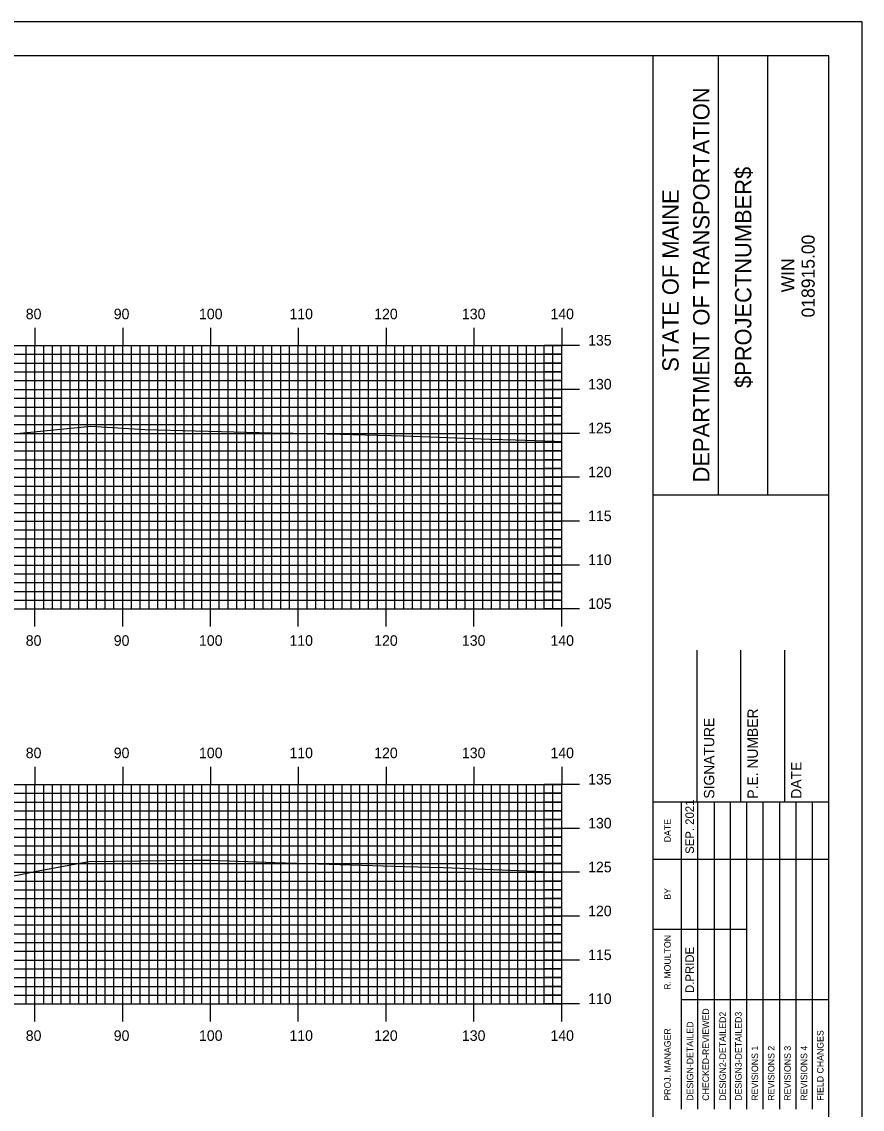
# Model space of a CAD drawing. Extents: x 843356 to 843699, y 363538 to 363758.
# Drawn here: x 843599.9 to 843695.6, y 363633.7 to 363757.6 of the extents above; entities that cross this region are included whole.
import ezdxf

# ---------------------------------------------------------------- set-up
doc = ezdxf.new("R2010")
doc.units = 0
for name, color, linetype in [('BORDER', 7, 'Continuous'), ('H_V ANNOTATION', 7, 'Continuous'), ('MAJOR', 7, 'Continuous'), ('MINOR', 7, 'Continuous'), ('PLOT BOUNDARY', 7, 'Continuous'), ('S_Roadway_Centerline', 7, 'Continuous')]:
    doc.layers.add(name, color=color, linetype=linetype)

msp = doc.modelspace()

# ---------------------------------------------------------------- linework, layer by layer
at = {"layer": 'BORDER'}
for p, q in [((843671.82, 363543.72), (843671.82, 363753.72)), ((843679.28, 363703.72), (843679.28, 363753.72)), ((843684.87, 363703.72), (843684.87, 363753.72)), ((843671.83, 363703.71), (843691.82, 363703.71)), ((843676.82, 363668.73), (843676.82, 363686.02)), ((843681.82, 363668.73), (843681.82, 363686.02)), ((843686.82, 363668.73), (843686.82, 363686.02)), ((843671.82, 363668.73), (843691.82, 363668.73))]:
    msp.add_line(p, q, dxfattribs=at)
msp.add_lwpolyline([(843371.82, 363543.72), (843691.82, 363543.72), (843691.82, 363753.72), (843371.82, 363753.72)], close=True, dxfattribs=at)
for points in [[(843675.05, 363662.23), (843675.05, 363668.73)], [(843676.92, 363633.73), (843676.92, 363668.73)], [(843678.78, 363668.73), (843678.78, 363633.73)], [(843680.65, 363633.73), (843680.65, 363668.73)], [(843682.51, 363633.73), (843682.51, 363668.73)], [(843684.37, 363633.73), (843684.37, 363668.73)], [(843686.24, 363633.73), (843686.24, 363668.73)], [(843688.1, 363633.73), (843688.1, 363668.73)], [(843689.96, 363633.73), (843689.96, 363668.73)], [(843675.06, 363633.73), (843675.06, 363667.31)], [(843671.82, 363662.23), (843691.82, 363662.23)], [(843671.82, 363654.23), (843675.06, 363654.23)], [(843675.05, 363654.23), (843682.51, 363654.23)], [(843675.05, 363646.23), (843691.82, 363646.23)]]:
    msp.add_lwpolyline(points, dxfattribs=at)
at = {"layer": 'MAJOR'}
for p, q in [((843601.42, 363722.73), (843601.42, 363720.72)), ((843611.42, 363722.73), (843611.42, 363720.72)), ((843621.42, 363722.73), (843621.42, 363720.72)), ((843631.42, 363722.73), (843631.42, 363720.72)), ((843641.42, 363722.73), (843641.42, 363720.72)), ((843651.42, 363722.73), (843651.42, 363720.72)), ((843661.42, 363722.73), (843661.42, 363720.72)), ((843381.42, 363720.72), (843661.42, 363720.72)), ((843381.42, 363720.72), (843661.42, 363720.72)), ((843601.42, 363690.72), (843601.42, 363720.72)), ((843611.42, 363690.72), (843611.42, 363720.72)), ((843621.42, 363690.72), (843621.42, 363720.72)), ((843631.42, 363690.72), (843631.42, 363720.72)), ((843641.42, 363690.72), (843641.42, 363720.72)), ((843651.42, 363690.72), (843651.42, 363720.72)), ((843663.43, 363720.72), (843659.42, 363720.72)), ((843661.42, 363690.72), (843661.42, 363720.72)), ((843661.42, 363690.72), (843661.42, 363720.72)), ((843381.42, 363715.72), (843661.42, 363715.72)), ((843663.43, 363715.72), (843659.42, 363715.72)), ((843381.42, 363710.72), (843661.42, 363710.72)), ((843663.43, 363710.72), (843659.42, 363710.72)), ((843381.42, 363705.72), (843661.42, 363705.72)), ((843663.43, 363705.72), (843659.42, 363705.72)), ((843381.42, 363700.72), (843661.42, 363700.72)), ((843663.43, 363700.72), (843659.42, 363700.72)), ((843381.42, 363695.72), (843661.42, 363695.72)), ((843663.43, 363695.72), (843659.42, 363695.72)), ((843381.42, 363690.72), (843661.42, 363690.72)), ((843381.42, 363690.72), (843661.42, 363690.72)), ((843601.42, 363688.72), (843601.42, 363690.72)), ((843611.42, 363688.72), (843611.42, 363690.72)), ((843621.42, 363688.72), (843621.42, 363690.72)), ((843631.42, 363688.72), (843631.42, 363690.72)), ((843641.42, 363688.72), (843641.42, 363690.72)), ((843651.42, 363688.72), (843651.42, 363690.72)), ((843663.43, 363690.72), (843659.42, 363690.72)), ((843661.42, 363688.72), (843661.42, 363690.72)), ((843601.42, 363672.73), (843601.42, 363670.72)), ((843611.42, 363672.73), (843611.42, 363670.72)), ((843621.42, 363672.73), (843621.42, 363670.72)), ((843631.42, 363672.73), (843631.42, 363670.72)), ((843641.42, 363672.73), (843641.42, 363670.72)), ((843651.42, 363672.73), (843651.42, 363670.72)), ((843661.42, 363672.73), (843661.42, 363670.72)), ((843381.42, 363670.72), (843661.42, 363670.72)), ((843381.42, 363670.72), (843661.42, 363670.72)), ((843601.42, 363645.72), (843601.42, 363670.72)), ((843611.42, 363645.72), (843611.42, 363670.72)), ((843621.42, 363645.72), (843621.42, 363670.72)), ((843631.42, 363645.72), (843631.42, 363670.72)), ((843641.42, 363645.72), (843641.42, 363670.72)), ((843651.42, 363645.72), (843651.42, 363670.72)), ((843663.43, 363670.72), (843659.42, 363670.72)), ((843661.42, 363645.72), (843661.42, 363670.72)), ((843661.42, 363645.72), (843661.42, 363670.72)), ((843381.42, 363665.72), (843661.42, 363665.72)), ((843663.43, 363665.72), (843659.42, 363665.72)), ((843381.42, 363660.72), (843661.42, 363660.72)), ((843663.43, 363660.72), (843659.42, 363660.72)), ((843381.42, 363655.72), (843661.42, 363655.72)), ((843663.43, 363655.72), (843659.42, 363655.72)), ((843381.42, 363650.72), (843661.42, 363650.72)), ((843663.43, 363650.72), (843659.42, 363650.72)), ((843381.42, 363645.72), (843661.42, 363645.72)), ((843381.42, 363645.72), (843661.42, 363645.72)), ((843601.42, 363643.72), (843601.42, 363645.72)), ((843611.42, 363643.72), (843611.42, 363645.72)), ((843621.42, 363643.72), (843621.42, 363645.72)), ((843631.42, 363643.72), (843631.42, 363645.72)), ((843641.42, 363643.72), (843641.42, 363645.72)), ((843651.42, 363643.72), (843651.42, 363645.72)), ((843663.43, 363645.72), (843659.42, 363645.72)), ((843661.42, 363643.72), (843661.42, 363645.72))]:
    msp.add_line(p, q, dxfattribs=at)
at = {"layer": 'MINOR'}
for p, q in [((843600.42, 363690.72), (843600.42, 363720.72)), ((843602.42, 363690.72), (843602.42, 363720.72)), ((843603.42, 363690.72), (843603.42, 363720.72)), ((843604.42, 363690.72), (843604.42, 363720.72)), ((843605.42, 363690.72), (843605.42, 363720.72)), ((843606.42, 363690.72), (843606.42, 363720.72)), ((843607.42, 363690.72), (843607.42, 363720.72)), ((843608.42, 363690.72), (843608.42, 363720.72)), ((843609.42, 363690.72), (843609.42, 363720.72)), ((843610.42, 363690.72), (843610.42, 363720.72)), ((843612.42, 363690.72), (843612.42, 363720.72)), ((843613.42, 363690.72), (843613.42, 363720.72)), ((843614.42, 363690.72), (843614.42, 363720.72)), ((843615.42, 363690.72), (843615.42, 363720.72)), ((843616.42, 363690.72), (843616.42, 363720.72)), ((843617.42, 363690.72), (843617.42, 363720.72)), ((843618.42, 363690.72), (843618.42, 363720.72)), ((843619.42, 363690.72), (843619.42, 363720.72)), ((843620.42, 363690.72), (843620.42, 363720.72)), ((843622.42, 363690.72), (843622.42, 363720.72)), ((843623.42, 363690.72), (843623.42, 363720.72)), ((843624.42, 363690.72), (843624.42, 363720.72)), ((843625.42, 363690.72), (843625.42, 363720.72)), ((843626.42, 363690.72), (843626.42, 363720.72)), ((843627.42, 363690.72), (843627.42, 363720.72)), ((843628.42, 363690.72), (843628.42, 363720.72)), ((843629.42, 363690.72), (843629.42, 363720.72)), ((843630.42, 363690.72), (843630.42, 363720.72)), ((843632.42, 363690.72), (843632.42, 363720.72)), ((843633.42, 363690.72), (843633.42, 363720.72)), ((843634.42, 363690.72), (843634.42, 363720.72)), ((843635.42, 363690.72), (843635.42, 363720.72)), ((843636.42, 363690.72), (843636.42, 363720.72)), ((843637.42, 363690.72), (843637.42, 363720.72)), ((843638.42, 363690.72), (843638.42, 363720.72)), ((843639.42, 363690.72), (843639.42, 363720.72)), ((843640.42, 363690.72), (843640.42, 363720.72)), ((843642.42, 363690.72), (843642.42, 363720.72)), ((843643.42, 363690.72), (843643.42, 363720.72)), ((843644.42, 363690.72), (843644.42, 363720.72)), ((843645.42, 363690.72), (843645.42, 363720.72)), ((843646.42, 363690.72), (843646.42, 363720.72)), ((843647.42, 363690.72), (843647.42, 363720.72)), ((843648.42, 363690.72), (843648.42, 363720.72)), ((843649.42, 363690.72), (843649.42, 363720.72)), ((843650.42, 363690.72), (843650.42, 363720.72)), ((843652.42, 363690.72), (843652.42, 363720.72)), ((843653.42, 363690.72), (843653.42, 363720.72)), ((843654.42, 363690.72), (843654.42, 363720.72)), ((843655.42, 363690.72), (843655.42, 363720.72)), ((843656.42, 363690.72), (843656.42, 363720.72)), ((843657.42, 363690.72), (843657.42, 363720.72)), ((843658.42, 363690.72), (843658.42, 363720.72)), ((843659.42, 363690.72), (843659.42, 363720.72)), ((843660.42, 363690.72), (843660.42, 363720.72)), ((843381.42, 363719.72), (843661.42, 363719.72)), ((843661.42, 363719.72), (843659.42, 363719.72)), ((843381.42, 363718.72), (843661.42, 363718.72)), ((843661.42, 363718.72), (843659.42, 363718.72)), ((843381.42, 363717.72), (843661.42, 363717.72)), ((843381.42, 363716.72), (843661.42, 363716.72)), ((843661.42, 363717.72), (843659.42, 363717.72)), ((843661.42, 363716.72), (843659.42, 363716.72)), ((843381.42, 363714.72), (843661.42, 363714.72)), ((843661.42, 363714.72), (843659.42, 363714.72)), ((843381.42, 363713.72), (843661.42, 363713.72)), ((843661.42, 363713.72), (843659.42, 363713.72)), ((843381.42, 363712.72), (843661.42, 363712.72)), ((843381.42, 363711.72), (843661.42, 363711.72)), ((843661.42, 363712.72), (843659.42, 363712.72)), ((843661.42, 363711.72), (843659.42, 363711.72)), ((843381.42, 363709.72), (843661.42, 363709.72)), ((843661.42, 363709.72), (843659.42, 363709.72)), ((843381.42, 363708.72), (843661.42, 363708.72)), ((843661.42, 363708.72), (843659.42, 363708.72)), ((843381.42, 363707.72), (843661.42, 363707.72)), ((843381.42, 363706.72), (843661.42, 363706.72)), ((843661.42, 363707.72), (843659.42, 363707.72)), ((843661.42, 363706.72), (843659.42, 363706.72)), ((843381.42, 363704.72), (843661.42, 363704.72)), ((843661.42, 363704.72), (843659.42, 363704.72)), ((843381.42, 363703.72), (843661.42, 363703.72)), ((843661.42, 363703.72), (843659.42, 363703.72)), ((843381.42, 363702.72), (843661.42, 363702.72)), ((843661.42, 363702.72), (843659.42, 363702.72)), ((843381.42, 363701.72), (843661.42, 363701.72)), ((843661.42, 363701.72), (843659.42, 363701.72)), ((843381.42, 363699.72), (843661.42, 363699.72)), ((843661.42, 363699.72), (843659.42, 363699.72)), ((843381.42, 363698.72), (843661.42, 363698.72)), ((843661.42, 363698.72), (843659.42, 363698.72)), ((843381.42, 363697.72), (843661.42, 363697.72)), ((843661.42, 363697.72), (843659.42, 363697.72)), ((843381.42, 363696.72), (843661.42, 363696.72)), ((843661.42, 363696.72), (843659.42, 363696.72)), ((843381.42, 363694.72), (843661.42, 363694.72)), ((843661.42, 363694.72), (843659.42, 363694.72)), ((843381.42, 363693.72), (843661.42, 363693.72)), ((843661.42, 363693.72), (843659.42, 363693.72)), ((843381.42, 363692.72), (843661.42, 363692.72)), ((843661.42, 363692.72), (843659.42, 363692.72)), ((843381.42, 363691.72), (843661.42, 363691.72)), ((843661.42, 363691.72), (843659.42, 363691.72)), ((843381.42, 363669.72), (843661.42, 363669.72)), ((843600.42, 363645.72), (843600.42, 363670.72)), ((843602.42, 363645.72), (843602.42, 363670.72)), ((843603.42, 363645.72), (843603.42, 363670.72)), ((843604.42, 363645.72), (843604.42, 363670.72)), ((843605.42, 363645.72), (843605.42, 363670.72)), ((843606.42, 363645.72), (843606.42, 363670.72)), ((843607.42, 363645.72), (843607.42, 363670.72)), ((843608.42, 363645.72), (843608.42, 363670.72)), ((843609.42, 363645.72), (843609.42, 363670.72)), ((843610.42, 363645.72), (843610.42, 363670.72)), ((843612.42, 363645.72), (843612.42, 363670.72)), ((843613.42, 363645.72), (843613.42, 363670.72)), ((843614.42, 363645.72), (843614.42, 363670.72)), ((843615.42, 363645.72), (843615.42, 363670.72)), ((843616.42, 363645.72), (843616.42, 363670.72)), ((843617.42, 363645.72), (843617.42, 363670.72)), ((843618.42, 363645.72), (843618.42, 363670.72)), ((843619.42, 363645.72), (843619.42, 363670.72)), ((843620.42, 363645.72), (843620.42, 363670.72)), ((843622.42, 363645.72), (843622.42, 363670.72)), ((843623.42, 363645.72), (843623.42, 363670.72)), ((843624.42, 363645.72), (843624.42, 363670.72)), ((843625.42, 363645.72), (843625.42, 363670.72)), ((843626.42, 363645.72), (843626.42, 363670.72)), ((843627.42, 363645.72), (843627.42, 363670.72)), ((843628.42, 363645.72), (843628.42, 363670.72)), ((843629.42, 363645.72), (843629.42, 363670.72)), ((843630.42, 363645.72), (843630.42, 363670.72)), ((843632.42, 363645.72), (843632.42, 363670.72)), ((843633.42, 363645.72), (843633.42, 363670.72)), ((843634.42, 363645.72), (843634.42, 363670.72)), ((843635.42, 363645.72), (843635.42, 363670.72)), ((843636.42, 363645.72), (843636.42, 363670.72)), ((843637.42, 363645.72), (843637.42, 363670.72)), ((843638.42, 363645.72), (843638.42, 363670.72)), ((843639.42, 363645.72), (843639.42, 363670.72)), ((843640.42, 363645.72), (843640.42, 363670.72)), ((843642.42, 363645.72), (843642.42, 363670.72)), ((843643.42, 363645.72), (843643.42, 363670.72)), ((843644.42, 363645.72), (843644.42, 363670.72)), ((843645.42, 363645.72), (843645.42, 363670.72)), ((843646.42, 363645.72), (843646.42, 363670.72)), ((843647.42, 363645.72), (843647.42, 363670.72)), ((843648.42, 363645.72), (843648.42, 363670.72)), ((843649.42, 363645.72), (843649.42, 363670.72)), ((843650.42, 363645.72), (843650.42, 363670.72)), ((843652.42, 363645.72), (843652.42, 363670.72)), ((843653.42, 363645.72), (843653.42, 363670.72)), ((843654.42, 363645.72), (843654.42, 363670.72)), ((843655.42, 363645.72), (843655.42, 363670.72)), ((843656.42, 363645.72), (843656.42, 363670.72)), ((843657.42, 363645.72), (843657.42, 363670.72)), ((843658.42, 363645.72), (843658.42, 363670.72)), ((843659.42, 363645.72), (843659.42, 363670.72)), ((843661.42, 363669.72), (843659.42, 363669.72)), ((843660.42, 363645.72), (843660.42, 363670.72)), ((843381.42, 363668.72), (843661.42, 363668.72)), ((843661.42, 363668.72), (843659.42, 363668.72)), ((843381.42, 363667.72), (843661.42, 363667.72)), ((843661.42, 363667.72), (843659.42, 363667.72)), ((843381.42, 363666.72), (843661.42, 363666.72)), ((843661.42, 363666.72), (843659.42, 363666.72)), ((843381.42, 363664.72), (843661.42, 363664.72)), ((843661.42, 363664.72), (843659.42, 363664.72)), ((843381.42, 363663.72), (843661.42, 363663.72)), ((843661.42, 363663.72), (843659.42, 363663.72)), ((843381.42, 363662.72), (843661.42, 363662.72)), ((843661.42, 363662.72), (843659.42, 363662.72)), ((843381.42, 363661.72), (843661.42, 363661.72)), ((843661.42, 363661.72), (843659.42, 363661.72)), ((843381.42, 363659.72), (843661.42, 363659.72)), ((843661.42, 363659.72), (843659.42, 363659.72)), ((843381.42, 363658.72), (843661.42, 363658.72)), ((843661.42, 363658.72), (843659.42, 363658.72)), ((843381.42, 363657.72), (843661.42, 363657.72)), ((843661.42, 363657.72), (843659.42, 363657.72)), ((843381.42, 363656.72), (843661.42, 363656.72)), ((843661.42, 363656.72), (843659.42, 363656.72)), ((843381.42, 363654.72), (843661.42, 363654.72)), ((843661.42, 363654.72), (843659.42, 363654.72)), ((843381.42, 363653.72), (843661.42, 363653.72)), ((843661.42, 363653.72), (843659.42, 363653.72)), ((843381.42, 363652.72), (843661.42, 363652.72)), ((843661.42, 363652.72), (843659.42, 363652.72)), ((843381.42, 363651.72), (843661.42, 363651.72)), ((843661.42, 363651.72), (843659.42, 363651.72)), ((843381.42, 363649.72), (843661.42, 363649.72)), ((843661.42, 363649.72), (843659.42, 363649.72)), ((843381.42, 363648.72), (843661.42, 363648.72)), ((843661.42, 363648.72), (843659.42, 363648.72)), ((843381.42, 363647.72), (843661.42, 363647.72)), ((843661.42, 363647.72), (843659.42, 363647.72)), ((843381.42, 363646.72), (843661.42, 363646.72)), ((843661.42, 363646.72), (843659.42, 363646.72))]:
    msp.add_line(p, q, dxfattribs=at)
at = {"layer": 'PLOT BOUNDARY'}
msp.add_lwpolyline([(843355.64, 363537.6), (843695.64, 363537.6), (843695.64, 363757.6), (843355.64, 363757.6)], close=True, dxfattribs=at)
at = {"layer": 'S_Roadway_Centerline'}
for points in [[(843597.86, 363710.54), (843607.79, 363711.53), (843613.93, 363711.17), (843628.42, 363710.76), (843633.26, 363710.71), (843643.42, 363710.42), (843653.22, 363710.06), (843656.15, 363709.98), (843660.63, 363709.83), (843661.42, 363709.8)], [(843594.41, 363659.36), (843601.78, 363660.88), (843607.58, 363661.94), (843616.45, 363662.07), (843619.49, 363662.09), (843621.46, 363662.09), (843628.76, 363661.84), (843643.53, 363661.37), (843647.97, 363661.28), (843660.33, 363660.76), (843661.42, 363660.72)]]:
    msp.add_lwpolyline(points, dxfattribs=at)

# ---------------------------------------------------------------- texts
at = {"layer": 'BORDER'}
for s, height, p in [('DEPARTMENT OF TRANSPORTATION', 1.8635, (843678.24, 363705.13)), ('$PROJECTNUMBER$', 1.8635, (843683.01, 363715.88)), ('STATE OF MAINE', 1.8635, (843674.73, 363717.74)), ('018915.00', 1.491, (843690.22, 363723.92)), ('WIN', 1.491, (843687.9, 363726.78)), ('SIGNATURE', 1.181, (843678.79, 363669.11)), ('P.E. NUMBER', 1.1811, (843683.75, 363669.11)), ('DATE', 1.181, (843688.71, 363669.11)), ('SEP. 2021', 0.969, (843676.47, 363662.82)), ('DATE', 0.743, (843673.83, 363664.14)), ('BY', 0.743, (843673.83, 363657.6)), ('R. MOULTON', 0.745, (843673.83, 363647.33)), ('D.PRIDE', 0.969, (843676.47, 363646.97)), ('CHECKED-REVIEWED', 0.7455, (843678.19, 363634.7)), ('DESIGN2-DETAILED2', 0.7455, (843680.12, 363634.7)), ('DESIGN3-DETAILED3', 0.7455, (843681.91, 363634.7)), ('DESIGN-DETAILED', 0.7455, (843676.4, 363634.7)), ('PROJ. MANAGER', 0.7455, (843673.83, 363634.7)), ('FIELD CHANGES', 0.7455, (843691.23, 363634.7)), ('REVISIONS 1', 0.7455, (843683.78, 363634.7)), ('REVISIONS 2', 0.7455, (843685.64, 363634.7)), ('REVISIONS 3', 0.7455, (843687.5, 363634.7)), ('REVISIONS 4', 0.7455, (843689.37, 363634.7))]:
    msp.add_text(s, height=height, rotation=90, dxfattribs=at).set_placement(p)
at = {"layer": 'H_V ANNOTATION'}
for s, p in [('80', (843600.38, 363723.72)), ('90', (843610.4, 363723.72)), ('100', (843620.11, 363723.72)), ('110', (843630.41, 363723.72)), ('120', (843640.06, 363723.72)), ('130', (843650.05, 363723.72)), ('140', (843660.13, 363723.72)), ('135', (843664.42, 363720.72)), ('130', (843664.42, 363715.72)), ('125', (843664.42, 363710.72)), ('120', (843664.42, 363705.72)), ('115', (843664.42, 363700.72)), ('110', (843664.42, 363695.72)), ('105', (843664.42, 363690.72)), ('80', (843600.38, 363686.52)), ('90', (843610.4, 363686.52)), ('100', (843620.11, 363686.52)), ('110', (843630.41, 363686.52)), ('120', (843640.06, 363686.52)), ('130', (843650.05, 363686.52)), ('140', (843660.13, 363686.52)), ('80', (843600.38, 363673.72)), ('90', (843610.4, 363673.72)), ('100', (843620.11, 363673.72)), ('110', (843630.41, 363673.72)), ('120', (843640.06, 363673.72)), ('130', (843650.05, 363673.72)), ('140', (843660.13, 363673.72)), ('135', (843664.42, 363670.72)), ('130', (843664.42, 363665.72)), ('125', (843664.42, 363660.72)), ('120', (843664.42, 363655.72)), ('115', (843664.42, 363650.72)), ('110', (843664.42, 363645.72)), ('80', (843600.38, 363641.52)), ('90', (843610.4, 363641.52)), ('100', (843620.11, 363641.52)), ('110', (843630.41, 363641.52)), ('120', (843640.06, 363641.52)), ('130', (843650.05, 363641.52)), ('140', (843660.13, 363641.52))]:
    msp.add_text(s, height=1.2, dxfattribs=at).set_placement(p)

doc.saveas('drawing.dxf')
